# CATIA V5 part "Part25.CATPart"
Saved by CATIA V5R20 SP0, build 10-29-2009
Part number: 8PF0642WB-00-RTECTO-20130117
Revision: ANY
Definition: UNKNOWN
Nomenclature: 8PF0642WB-00-RTECTO-20130117
Source: Unknown
Bounding box of the stored display mesh (mm): x 1758.686 to 1958.686, y 1414.697 to 1418.697, z 0 to 6
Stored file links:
  C:\Users\Utente\Desktop\IO LAVORO\3D X SITO CF\CUMSA\3D files PF\PF 064200\Part25.CATPart
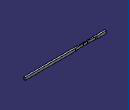
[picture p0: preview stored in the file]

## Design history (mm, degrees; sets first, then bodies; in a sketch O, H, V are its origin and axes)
Body1 "Cortar-Extruir1" (main body)
  Solid1: solid without history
